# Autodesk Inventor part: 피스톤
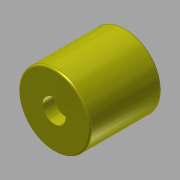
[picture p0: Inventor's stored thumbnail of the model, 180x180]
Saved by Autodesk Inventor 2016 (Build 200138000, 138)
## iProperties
Created: 2018-01
Part Number: 피스톤
Material: 강철, 탄소
Document SubType Name: Modeling
Designer: mduedu
Density: 7.87 g/cm^3
Appearance: 노란색
Mass: 44.9853 g
Surface Area: 21.9333 cm^2
Volume: 5.71605 cm^3
Author: mduedu
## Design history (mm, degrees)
sketch "스케치1"
  geometry: C1 r 10 at (0, 0); 1 further point
  constraints: 1 centre point, 1 coincident
  dimensions: "d0" = 20 diameter of C1
extrude "돌출1" new body sketch "스케치1" distance "d1" = 20; taper "d2" = 0 deg
hole "구멍1" diameter "d5" = 7; stored, may be unused: countersink angle "d9" = 90 deg, drill point angle "d11" = 0 deg; dims "d6" = 6, "d7" = 4, "d8" = 2, "d10" = 10, "d12" = 10, "d13" = 10
chamfer "모따기1" distance "d14" = 0.5; stored, may be unused: second distance "d15" = 2, angle "d16" = 45 deg
fillet "모깎기1" dims "d17" = 0.5
sketch "스케치2"
  geometry: 2 further points
  constraints: 1 coincident
sketch "스케치3"
  geometry: 2 further points
  constraints: 1 coincident
hole "구멍2" sketch "스케치3" at (0, 0) diameter "d18" = 3.4; stored, may be unused: countersink angle "d22" = 90 deg, drill point angle "d24" = 0 deg; dims "d19" = 6, "d20" = 6.5, "d21" = 3.4, "d23" = 8
node "솔리드1"
